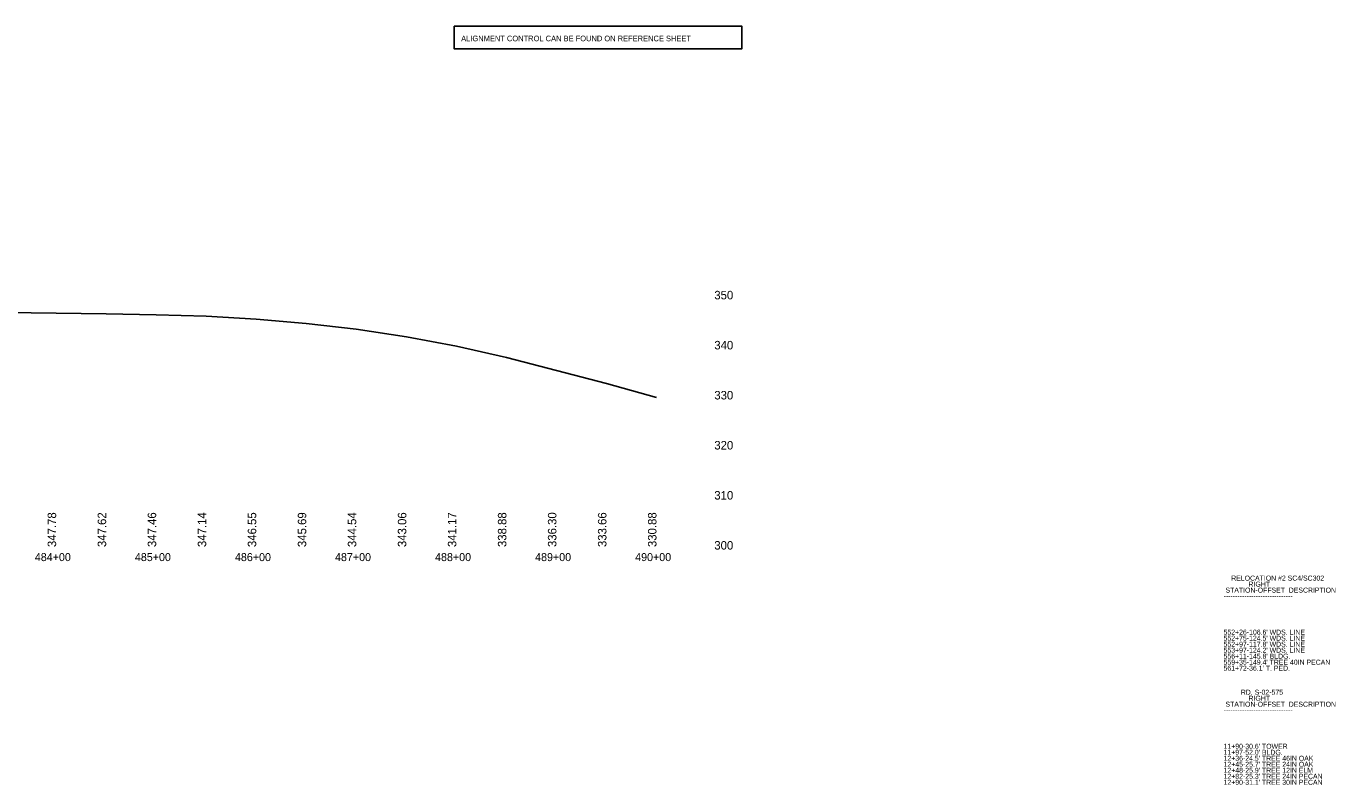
# Model space of a CAD drawing. Extents: x 48556 to 51363, y 45290 to 53458.
# Drawn here: x 50058 to 51363, y 45290 to 46048 of the extents above; entities that cross this region are included whole.
import ezdxf

# ---------------------------------------------------------------- set-up
doc = ezdxf.new("R2010")
doc.units = 0
for name, color, linetype in [('Level 24', 7, 'Continuous'), ('Level 25', 7, 'Continuous'), ('Level 40', 7, 'Continuous'), ('Level 42', 7, 'Continuous'), ('Level 43', 7, 'Continuous')]:
    doc.layers.add(name, color=color, linetype=linetype)

msp = doc.modelspace()

# ---------------------------------------------------------------- linework, layer by layer
at = {"layer": 'Level 25'}
msp.add_lwpolyline([(50485.8, 46048.4), (50773.1, 46048.4), (50773.1, 46025.7), (50485.8, 46025.7)], close=True, dxfattribs=at)
at = {"layer": 'Level 40'}
msp.add_lwpolyline([(49187.9, 45754.1), (49737.9, 45767.5), (49787.9, 45766.3), (49787.9, 45766.3), (49887.7, 45764.7), (49887.9, 45764.7), (49937.9, 45763.8), (49987.9, 45762.9), (50037.9, 45762.2), (50087.9, 45761.7), (50137.9, 45760.9), (50187.9, 45760.1), (50237.9, 45758.5), (50287.9, 45755.6), (50337.9, 45751.3), (50387.9, 45745.5), (50437.9, 45738.1), (50487.9, 45728.7), (50537.9, 45717.2), (50587.9, 45704.4), (50637.9, 45691.2), (50687.9, 45677.2)], dxfattribs=at)

# ---------------------------------------------------------------- texts
at = {"layer": 'Level 24'}
for s, p in [('    RELOCATION #2 SC4/SC302   ', (51254.7, 45494.4)), (' STATION-OFFSET  DESCRIPTION', (51254.7, 45482.4)), ('             RIGHT            ', (51254.7, 45488.4)), ('------------------------------', (51254.7, 45476.4)), ("552+26-106.6' WDS. LINE", (51254.7, 45440.4)), ("552+75-124.5' WDS. LINE", (51254.7, 45434.4)), ("552+97-117.8' WDS. LINE", (51254.7, 45428.4)), ("553+97-124.2' WDS. LINE", (51254.7, 45422.4)), ("556+11-145.8' BLDG.", (51254.7, 45416.4)), ("559+35-149.4' TREE 40IN PECAN", (51254.7, 45410.4)), ("561+72-36.1' T. PED.", (51254.7, 45404.4)), ('         RD. S-02-575         ', (51254.7, 45380.4)), ('             RIGHT            ', (51254.7, 45374.4)), (' STATION-OFFSET  DESCRIPTION', (51254.7, 45368.4)), ('------------------------------', (51254.7, 45362.4)), ("11+90-30.6' TOWER", (51254.7, 45326.4)), ("11+97-52.0' BLDG.", (51254.7, 45320.4)), ("12+36-24.5' TREE 46IN OAK", (51254.7, 45314.4)), ("12+45-25.7' TREE 24IN OAK", (51254.7, 45308.4)), ("12+48-25.9' TREE 12IN ELM", (51254.7, 45302.4)), ("12+82-25.3' TREE 24IN PECAN", (51254.7, 45296.4)), ("12+90-31.1' TREE 30IN PECAN", (51254.7, 45290.4))]:
    msp.add_text(s, height=5, dxfattribs=at).set_placement(p)
at = {"layer": 'Level 25'}
msp.add_text('ALIGNMENT CONTROL CAN BE FOUND ON REFERENCE SHEET', height=5.6, dxfattribs=at).set_placement((50492.7, 46033.3))
at = {"layer": 'Level 42'}
for s, height, p in [('350', 8.5, (50745.7, 45775.4)), ('340', 8.5, (50745.7, 45725.4)), ('330', 8.5, (50745.7, 45675.4)), ('320', 8.5, (50745.7, 45625.4)), ('310', 8.5, (50745.7, 45575.4)), ('484+00', 8, (50066.6, 45513.9)), ('485+00', 8, (50166.6, 45513.9)), ('486+00', 8, (50266.6, 45513.9)), ('487+00', 8, (50366.6, 45513.9)), ('488+00', 8, (50466.6, 45513.9)), ('489+00', 8, (50566.6, 45513.9)), ('490+00', 8, (50666.6, 45513.9)), ('300', 8.5, (50745.7, 45525.4))]:
    msp.add_text(s, height=height, dxfattribs=at).set_placement(p)
at = {"layer": 'Level 43'}
for s, p in [('347.78', (50087.9, 45527.9)), ('347.62', (50137.9, 45527.9)), ('347.46', (50187.9, 45527.9)), ('347.14', (50237.9, 45527.9)), ('346.55', (50287.9, 45527.9)), ('345.69', (50337.9, 45527.9)), ('344.54', (50387.9, 45527.9)), ('343.06', (50437.9, 45527.9)), ('341.17', (50487.9, 45527.9)), ('338.88', (50537.9, 45527.9)), ('336.30', (50587.9, 45527.9)), ('333.66', (50637.9, 45527.9)), ('330.88', (50687.9, 45527.9))]:
    msp.add_text(s, height=8.5, rotation=90, dxfattribs=at).set_placement(p)

doc.saveas('drawing.dxf')
